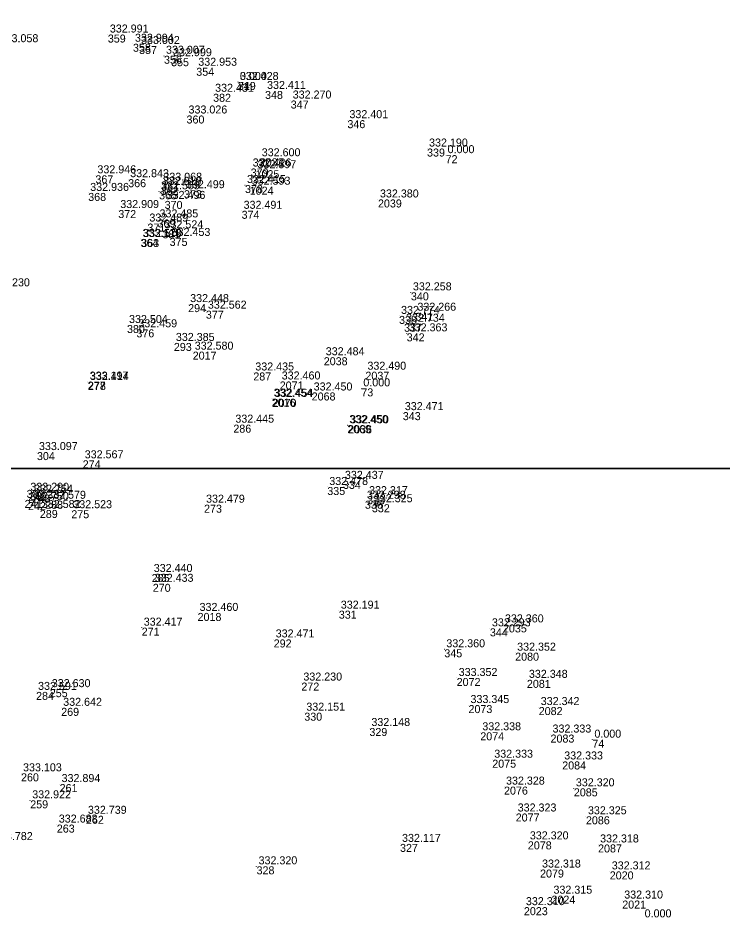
# Model space of a CAD drawing. Extents: x -829398 to -819400, y -1074439 to -1067977.
# Drawn here: x -819669.5 to -819563.9, y -1073067.5 to -1072932.5 of the extents above; entities that cross this region are included whole.
import ezdxf

# ---------------------------------------------------------------- set-up
doc = ezdxf.new("R2010")
doc.units = 0
for name, color, linetype in [('Vrstva 60', 7, 'Continuous'), ('Vrstva 61', 7, 'Continuous'), ('Čísla bodů_doměření_2012', 7, 'Continuous')]:
    doc.layers.add(name, color=color, linetype=linetype)

# ---------------------------------------------------------------- blocks, each defined once
blk = doc.blocks.new('BOD')
at = {"layer": 'Čísla bodů_doměření_2012'}
for p, q in [((-0.15, 0), (0.15, 0)), ((0, -0.15), (0, 0.15))]:
    blk.add_line(p, q, dxfattribs=at)

msp = doc.modelspace()

# ---------------------------------------------------------------- linework, layer by layer
at = {"layer": 'Vrstva 61'}
for points in [[(-819400, -1072500), (-820100, -1072500), (-820100, -1073000), (-819400, -1073000)], [(-819500, -1073000), (-820200, -1073000), (-820200, -1073500), (-819500, -1073500)]]:
    msp.add_lwpolyline(points, close=True, dxfattribs=at)

# ---------------------------------------------------------------- block references
at = {"layer": 'Vrstva 60', "xscale": 0.010000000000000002, "yscale": 0.010000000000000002}
for p in [(-819656.083, -1072934.983), (-819652.317, -1072936.364), (-819651.402, -1072936.699), (-819647.67, -1072938.162), (-819646.608, -1072938.527), (-819642.834, -1072939.963), (-819636.607, -1072942.092), (-819636.587, -1072942.091), (-819640.314, -1072943.862), (-819632.534, -1072943.439), (-819628.688, -1072944.874), (-819644.296, -1072947.118), (-819620.197, -1072947.818), (-819608.266, -1072952.07), (-819633.33, -1072953.53), (-819605.486, -1072953.064), (-819657.945, -1072956.081), (-819634.686, -1072955.062), (-819633.962, -1072955.318), (-819653.035, -1072956.664), (-819648.068, -1072957.196), (-819635.537, -1072957.539), (-819659.02, -1072958.723), (-819648.407, -1072958.485), (-819648.173, -1072957.817), (-819644.678, -1072958.315), (-819634.834, -1072957.787), (-819647.573, -1072959.919), (-819615.62, -1072959.7), (-819654.518, -1072961.288), (-819636.046, -1072961.399), (-819648.639, -1072962.693), (-819650.156, -1072963.312), (-819647.896, -1072964.322), (-819651.176, -1072965.617), (-819651.084, -1072965.633), (-819646.825, -1072965.47), (-819610.686, -1072973.622), (-819644.05, -1072975.385), (-819641.398, -1072976.369), (-819612.459, -1072977.153), (-819610.014, -1072976.679), (-819653.21, -1072978.52), (-819651.809, -1072979.162), (-819611.717, -1072978.328), (-819611.318, -1072979.767), (-819646.192, -1072981.206), (-819643.37, -1072982.51), (-819623.74, -1072983.35), (-819634.292, -1072985.632), (-819617.5, -1072985.52), (-819659.097, -1072986.996), (-819659.058, -1072987.063), (-819630.34, -1072986.98), (-819625.55, -1072988.63), (-819618.112, -1072988.011), (-819631.54, -1072989.55), (-819631.4, -1072989.6), (-819611.902, -1072991.577), (-819637.28, -1072993.453), (-819620.21, -1072993.52), (-819620.09, -1072993.56), (-819666.698, -1072997.561), (-819659.846, -1072998.796), (-819620.869, -1073001.878), (-819620.869, -1073001.878), (-819623.212, -1073002.795), (-819623.212, -1073002.795), (-819668.547, -1073004.73), (-819668.547, -1073004.73), (-819667.995, -1073003.661), (-819667.995, -1073003.661), (-819667.416, -1073003.951), (-819667.416, -1073003.951), (-819665.468, -1073004.859), (-819665.468, -1073004.859), (-819617.576, -1073004.855), (-819617.576, -1073004.855), (-819617.255, -1073004.171), (-819617.255, -1073004.171), (-819668.039, -1073005.058), (-819668.039, -1073005.058), (-819641.669, -1073005.45), (-819641.669, -1073005.45), (-819616.53, -1073005.381), (-819616.53, -1073005.381), (-819666.269, -1073006.237), (-819666.269, -1073006.237), (-819661.554, -1073006.277), (-819661.554, -1073006.277), (-819649.507, -1073015.84), (-819649.507, -1073015.84), (-819649.352, -1073017.307), (-819649.352, -1073017.307), (-819642.64, -1073021.67), (-819642.64, -1073021.67), (-819621.488, -1073021.329), (-819621.488, -1073021.329), (-819596.9, -1073023.39), (-819596.9, -1073023.39), (-819651.007, -1073023.881), (-819651.007, -1073023.881), (-819598.852, -1073023.982), (-819598.852, -1073023.982), (-819631.24, -1073025.641), (-819631.24, -1073025.641), (-819605.678, -1073027.12), (-819605.678, -1073027.12), (-819595.07, -1073027.63), (-819595.07, -1073027.63), (-819603.83, -1073031.42), (-819603.83, -1073031.42), (-819593.31, -1073031.7), (-819593.31, -1073031.7), (-819664.779, -1073033.095), (-819664.779, -1073033.095), (-819627.093, -1073032.108), (-819627.093, -1073032.108), (-819666.832, -1073033.506), (-819666.832, -1073033.506), (-819663.067, -1073035.894), (-819663.067, -1073035.894), (-819602.06, -1073035.48), (-819602.06, -1073035.48), (-819591.54, -1073035.78), (-819591.54, -1073035.78), (-819626.654, -1073036.622), (-819626.654, -1073036.622), (-819616.905, -1073038.919), (-819616.905, -1073038.919), (-819600.29, -1073039.56), (-819600.29, -1073039.56), (-819589.77, -1073039.9), (-819589.77, -1073039.9), (-819583.5, -1073040.667), (-819598.5, -1073043.67), (-819598.5, -1073043.67), (-819588.02, -1073043.93), (-819588.02, -1073043.93), (-819669.085, -1073045.707), (-819669.085, -1073045.707), (-819663.308, -1073047.321), (-819663.308, -1073047.321), (-819596.74, -1073047.7), (-819596.74, -1073047.7), (-819586.28, -1073047.96), (-819586.28, -1073047.96), (-819667.707, -1073049.759), (-819667.707, -1073049.759), (-819659.364, -1073052.077), (-819659.364, -1073052.077), (-819594.99, -1073051.73), (-819594.99, -1073051.73), (-819663.728, -1073053.393), (-819663.728, -1073053.393), (-819584.47, -1073052.15), (-819584.47, -1073052.15), (-819593.17, -1073055.91), (-819593.17, -1073055.91), (-819612.317, -1073056.289), (-819612.317, -1073056.289), (-819582.65, -1073056.37), (-819582.65, -1073056.37), (-819633.804, -1073059.65), (-819633.804, -1073059.65), (-819591.34, -1073060.13), (-819591.34, -1073060.13), (-819580.9, -1073060.41), (-819580.9, -1073060.41), (-819589.63, -1073064.05), (-819589.63, -1073064.05), (-819579.03, -1073064.78), (-819579.03, -1073064.78), (-819593.76, -1073065.77), (-819593.76, -1073065.77)]:
    msp.add_blockref('BOD', p, dxfattribs=at)

# ---------------------------------------------------------------- texts
at = {"layer": 'Vrstva 60'}
for s, p in [('359', (-819656.083, -1072936.183)), ('358', (-819652.317, -1072937.564)), ('357', (-819651.402, -1072937.899)), ('356', (-819647.67, -1072939.362)), ('355', (-819646.608, -1072939.727)), ('354', (-819642.834, -1072941.163)), ('349', (-819636.607, -1072943.292)), ('71', (-819636.587, -1072943.291)), ('382', (-819640.314, -1072945.062)), ('348', (-819632.534, -1072944.639)), ('347', (-819628.688, -1072946.074)), ('360', (-819644.296, -1072948.318)), ('346', (-819620.197, -1072949.018)), ('339', (-819608.266, -1072953.27)), ('2033', (-819633.33, -1072954.73)), ('72', (-819605.486, -1072954.264)), ('367', (-819657.945, -1072957.281)), ('379', (-819634.686, -1072956.262)), ('1025', (-819633.962, -1072956.518)), ('366', (-819653.035, -1072957.864)), ('361', (-819648.068, -1072958.396)), ('378', (-819635.537, -1072958.739)), ('368', (-819659.02, -1072959.923)), ('365', (-819648.407, -1072959.685)), ('362', (-819648.173, -1072959.017)), ('373', (-819644.678, -1072959.515)), ('1024', (-819634.834, -1072958.987)), ('370', (-819647.573, -1072961.119)), ('2039', (-819615.62, -1072960.9)), ('372', (-819654.518, -1072962.488)), ('374', (-819636.046, -1072962.599)), ('369', (-819648.639, -1072963.893)), ('371', (-819650.156, -1072964.512)), ('381', (-819647.896, -1072965.522)), ('364', (-819651.176, -1072966.817)), ('363', (-819651.084, -1072966.833)), ('375', (-819646.825, -1072966.67)), ('340', (-819610.686, -1072974.822)), ('294', (-819644.05, -1072976.585)), ('377', (-819641.398, -1072977.569)), ('338', (-819612.459, -1072978.353)), ('341', (-819610.014, -1072977.879)), ('380', (-819653.21, -1072979.72)), ('376', (-819651.809, -1072980.362)), ('337', (-819611.717, -1072979.528)), ('342', (-819611.318, -1072980.967)), ('293', (-819646.192, -1072982.406)), ('2017', (-819643.37, -1072983.71)), ('2038', (-819623.74, -1072984.55)), ('287', (-819634.292, -1072986.832)), ('2037', (-819617.5, -1072986.72)), ('277', (-819659.097, -1072988.196)), ('278', (-819659.058, -1072988.263)), ('2071', (-819630.34, -1072988.18)), ('2068', (-819625.55, -1072989.83)), ('73', (-819618.112, -1072989.211)), ('2016', (-819631.54, -1072990.75)), ('2070', (-819631.4, -1072990.8)), ('343', (-819611.902, -1072992.777)), ('286', (-819637.28, -1072994.653)), ('2069', (-819620.21, -1072994.72)), ('2036', (-819620.09, -1072994.76)), ('304', (-819666.698, -1072998.761)), ('274', (-819659.846, -1072999.996)), ('334', (-819620.869, -1073003.078)), ('335', (-819623.212, -1073003.995)), ('241', (-819668.547, -1073005.93)), ('240', (-819667.995, -1073004.861)), ('243', (-819667.416, -1073005.151)), ('288', (-819665.468, -1073006.059)), ('336', (-819617.576, -1073006.055)), ('333', (-819617.255, -1073005.371)), ('242', (-819668.039, -1073006.258)), ('289', (-819666.269, -1073007.437)), ('273', (-819641.669, -1073006.65)), ('332', (-819616.53, -1073006.581)), ('275', (-819661.554, -1073007.477)), ('285', (-819649.507, -1073017.04)), ('270', (-819649.352, -1073018.507)), ('2018', (-819642.64, -1073022.87)), ('331', (-819621.488, -1073022.529)), ('2035', (-819596.9, -1073024.59)), ('271', (-819651.007, -1073025.081)), ('344', (-819598.852, -1073025.182)), ('292', (-819631.24, -1073026.841)), ('345', (-819605.678, -1073028.32)), ('2080', (-819595.07, -1073028.83)), ('2072', (-819603.83, -1073032.62)), ('2081', (-819593.31, -1073032.9)), ('255', (-819664.779, -1073034.295)), ('272', (-819627.093, -1073033.308)), ('284', (-819666.832, -1073034.706)), ('269', (-819663.067, -1073037.094)), ('2073', (-819602.06, -1073036.68)), ('2082', (-819591.54, -1073036.98)), ('330', (-819626.654, -1073037.822)), ('329', (-819616.905, -1073040.119)), ('2074', (-819600.29, -1073040.76)), ('2083', (-819589.77, -1073041.1)), ('74', (-819583.5, -1073041.867)), ('2075', (-819598.5, -1073044.87)), ('2084', (-819588.02, -1073045.13)), ('260', (-819669.085, -1073046.907)), ('261', (-819663.308, -1073048.521)), ('2076', (-819596.74, -1073048.9)), ('2085', (-819586.28, -1073049.16)), ('259', (-819667.707, -1073050.959)), ('262', (-819659.364, -1073053.277)), ('2077', (-819594.99, -1073052.93)), ('2086', (-819584.47, -1073053.35)), ('263', (-819663.728, -1073054.593)), ('2078', (-819593.17, -1073057.11)), ('327', (-819612.317, -1073057.489)), ('2087', (-819582.65, -1073057.57)), ('328', (-819633.804, -1073060.85)), ('2079', (-819591.34, -1073061.33)), ('2020', (-819580.9, -1073061.61)), ('2024', (-819589.63, -1073065.25)), ('2021', (-819579.03, -1073065.98)), ('2023', (-819593.76, -1073066.97))]:
    msp.add_text(s, height=1.2, dxfattribs=at).set_placement(p)
at = {"layer": 'Vrstva 61'}
for s, p in [('332.991', (-819655.783, -1072934.683)), ('333.058', (-819672.291, -1072936.133)), ('332.994', (-819652.017, -1072936.064)), ('333.002', (-819651.102, -1072936.399)), ('333.007', (-819647.37, -1072937.862)), ('332.999', (-819646.308, -1072938.227)), ('332.953', (-819642.534, -1072939.663)), ('332.428', (-819636.307, -1072941.792)), ('0.000', (-819636.287, -1072941.791)), ('332.431', (-819640.014, -1072943.562)), ('332.411', (-819632.234, -1072943.139)), ('332.270', (-819628.388, -1072944.574)), ('333.026', (-819643.996, -1072946.818)), ('332.401', (-819619.897, -1072947.518)), ('332.190', (-819607.966, -1072951.77)), ('332.600', (-819633.03, -1072953.23)), ('0.000', (-819605.186, -1072952.764)), ('332.426', (-819634.386, -1072954.762)), ('332.946', (-819657.645, -1072955.781)), ('332.597', (-819633.662, -1072955.018)), ('332.843', (-819652.735, -1072956.364)), ('333.068', (-819647.768, -1072956.896)), ('332.415', (-819635.237, -1072957.239)), ('332.593', (-819634.534, -1072957.487)), ('332.936', (-819658.72, -1072958.423)), ('332.509', (-819648.107, -1072958.185)), ('332.619', (-819647.873, -1072957.517)), ('332.499', (-819644.378, -1072958.015)), ('332.496', (-819647.273, -1072959.619)), ('332.380', (-819615.32, -1072959.4)), ('332.909', (-819654.218, -1072960.988)), ('332.491', (-819635.746, -1072961.099)), ('332.485', (-819648.339, -1072962.393)), ('332.489', (-819649.856, -1072963.012)), ('332.524', (-819647.596, -1072964.022)), ('333.113', (-819650.876, -1072965.317)), ('332.570', (-819650.784, -1072965.333)), ('332.453', (-819646.525, -1072965.17)), ('333.230', (-819673.56, -1072972.72)), ('332.258', (-819610.386, -1072973.322)), ('332.448', (-819643.75, -1072975.085)), ('332.562', (-819641.098, -1072976.069)), ('332.266', (-819609.714, -1072976.379)), ('332.774', (-819612.159, -1072976.853)), ('332.504', (-819652.91, -1072978.22)), ('332.459', (-819651.509, -1072978.862)), ('332.734', (-819611.417, -1072978.028)), ('332.363', (-819611.018, -1072979.467)), ('332.385', (-819645.892, -1072980.906)), ('332.580', (-819643.07, -1072982.21)), ('332.484', (-819623.44, -1072983.05)), ('332.435', (-819633.992, -1072985.332)), ('332.490', (-819617.2, -1072985.22)), ('333.197', (-819658.797, -1072986.696)), ('332.414', (-819658.758, -1072986.763)), ('332.460', (-819630.04, -1072986.68)), ('332.450', (-819625.25, -1072988.33)), ('0.000', (-819617.812, -1072987.711)), ('332.454', (-819631.24, -1072989.25)), ('332.454', (-819631.1, -1072989.3)), ('332.471', (-819611.602, -1072991.277)), ('332.445', (-819636.98, -1072993.153)), ('332.450', (-819619.91, -1072993.22)), ('332.450', (-819619.79, -1072993.26)), ('333.097', (-819666.398, -1072997.261)), ('332.567', (-819659.546, -1072998.496)), ('332.437', (-819620.569, -1073001.578)), ('333.290', (-819667.695, -1073003.361)), ('332.478', (-819622.912, -1073002.495)), ('333.287', (-819668.247, -1073004.43)), ('332.754', (-819667.116, -1073003.651)), ('332.579', (-819665.168, -1073004.559)), ('332.298', (-819617.276, -1073004.555)), ('332.317', (-819616.955, -1073003.871)), ('332.750', (-819667.739, -1073004.758)), ('332.582', (-819665.969, -1073005.937)), ('332.523', (-819661.254, -1073005.977)), ('332.479', (-819641.369, -1073005.15)), ('332.325', (-819616.23, -1073005.081)), ('332.440', (-819649.207, -1073015.54)), ('332.433', (-819649.052, -1073017.007)), ('332.460', (-819642.34, -1073021.37)), ('332.191', (-819621.188, -1073021.029)), ('332.417', (-819650.707, -1073023.581)), ('332.360', (-819596.6, -1073023.09)), ('332.293', (-819598.552, -1073023.682)), ('332.471', (-819630.94, -1073025.341)), ('332.360', (-819605.378, -1073026.82)), ('332.352', (-819594.77, -1073027.33)), ('333.352', (-819603.53, -1073031.12)), ('332.348', (-819593.01, -1073031.4)), ('332.630', (-819664.479, -1073032.795)), ('332.230', (-819626.793, -1073031.808)), ('332.591', (-819666.532, -1073033.206)), ('332.642', (-819662.767, -1073035.594)), ('333.345', (-819601.76, -1073035.18)), ('332.342', (-819591.24, -1073035.48)), ('332.151', (-819626.354, -1073036.322)), ('332.148', (-819616.605, -1073038.619)), ('332.338', (-819599.99, -1073039.26)), ('332.333', (-819589.47, -1073039.6)), ('0.000', (-819583.2, -1073040.367)), ('332.333', (-819598.2, -1073043.37)), ('332.333', (-819587.72, -1073043.63)), ('333.103', (-819668.785, -1073045.407)), ('332.894', (-819663.008, -1073047.021)), ('332.328', (-819596.44, -1073047.4)), ('332.320', (-819585.98, -1073047.66)), ('332.922', (-819667.407, -1073049.459)), ('332.739', (-819659.064, -1073051.777)), ('332.323', (-819594.69, -1073051.43)), ('332.325', (-819584.17, -1073051.85)), ('332.683', (-819663.428, -1073053.093)), ('333.782', (-819673.134, -1073055.716)), ('332.117', (-819612.017, -1073055.989)), ('332.320', (-819592.87, -1073055.61)), ('332.318', (-819582.35, -1073056.07)), ('332.320', (-819633.504, -1073059.35)), ('332.318', (-819591.04, -1073059.83)), ('332.312', (-819580.6, -1073060.11)), ('332.315', (-819589.33, -1073063.75)), ('332.310', (-819593.46, -1073065.47)), ('332.310', (-819578.73, -1073064.48)), ('0.000', (-819575.674, -1073067.299))]:
    msp.add_text(s, height=1.2, dxfattribs=at).set_placement(p)

doc.saveas('drawing.dxf')
